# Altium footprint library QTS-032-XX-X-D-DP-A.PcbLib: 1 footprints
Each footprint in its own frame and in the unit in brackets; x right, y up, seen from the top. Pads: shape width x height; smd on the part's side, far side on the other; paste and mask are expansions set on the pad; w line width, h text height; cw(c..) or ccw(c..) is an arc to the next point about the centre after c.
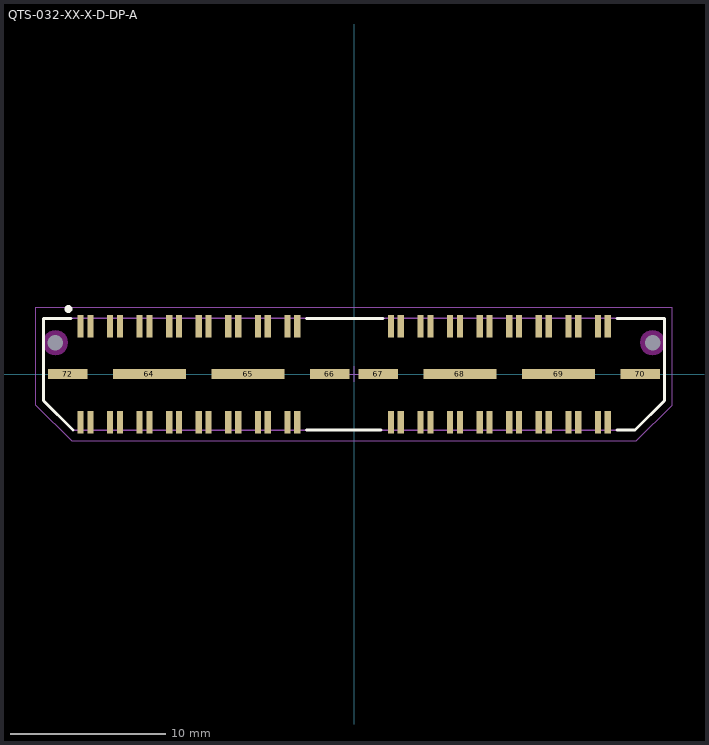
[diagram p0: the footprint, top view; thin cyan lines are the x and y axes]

## QTS-032-XX-X-D-DP-A [mm] "0.635mm pitch, 64 pin, high speed terminal; differential pair array"
height 4.27
pads (74):
  rect 0.4x1.45 smd mask+0: 1(-17.621,3.086) 2(-17.621,-3.086) 3(-16.986,3.086) 4(-16.986,-3.086) 5(-15.716,3.086) 6(-15.716,-3.086) 7(-15.081,3.086) 8(-15.081,-3.086) 9(-13.811,3.086) 10(-13.811,-3.086) 11(-13.176,3.086) 12(-13.176,-3.086) 13(-11.906,3.086) 14(-11.906,-3.086) 15(-11.271,3.086) 16(-11.271,-3.086) 17(-10.001,3.086) 18(-10.001,-3.086) 19(-9.366,3.086) 20(-9.366,-3.086) 21(-8.096,3.086) 22(-8.096,-3.086) 23(-7.461,3.086) 24(-7.461,-3.086) 25(-6.191,3.086) 26(-6.191,-3.086) 27(-5.556,3.086) 28(-5.556,-3.086) 29(-4.286,3.086) 30(-4.286,-3.086) 31(-3.651,3.086) 32(-3.651,-3.086) 33(2.381,3.086) 34(2.381,-3.086) 35(3.016,3.086) 36(3.016,-3.086) 37(4.286,3.086) 38(4.286,-3.086) 39(4.921,3.086) 40(4.921,-3.086) 41(6.191,3.086) 42(6.191,-3.086) 43(6.826,3.086) 44(6.826,-3.086) 45(8.096,3.086) 46(8.096,-3.086) 47(8.731,3.086) 48(8.731,-3.086) 49(10.001,3.086) 50(10.001,-3.086) 51(10.636,3.086) 52(10.636,-3.086) 53(11.906,3.086) 54(11.906,-3.086) 55(12.541,3.086) 56(12.541,-3.086) 57(13.811,3.086) 58(13.811,-3.086) 59(14.446,3.086) 60(14.446,-3.086) 61(15.716,3.086) 62(15.716,-3.086) 63(16.351,3.086) 71(16.351,-3.086)
  rect 4.7x0.65 smd mask+0: 64(-13.176,0) 65(-6.826,0) 68(6.826,0) 69(13.176,0)
  rect 2.55x0.65 smd mask+0: 66(-1.556,0) 67(1.556,0) 70(18.447,0) 72(-18.447,0)
  round 0.5 hole 1 unplated mask+0: 73(-19.241,2.032) 74(19.241,2.032)
Top Overlay:
  circle w0.25: c-18.4,4.2 r0.125
  lines w0.2: -18.25,3.6 -20,3.6 -20,-1.7 -18.1,-3.6 ; -3.05,-3.6 1.75,-3.6 ; -3.05,3.6 1.85,3.6 ; 16.95,-3.6 18.1,-3.6 20,-1.7 20,3.6 16.95,3.6
Keep-Out Layer:
  pour cut-out: -18.434,2.032 -18.462,2.241 -18.542,2.435 -18.67,2.603 -18.838,2.731 -19.032,2.811 -19.241,2.839 -19.45,2.811 -19.644,2.731 -19.812,2.603 -19.94,2.435 -20.02,2.241 -20.048,2.032 -20.02,1.823 -19.94,1.629 -19.812,1.461 -19.644,1.333 -19.45,1.253 -19.241,1.225 -19.032,1.253 -18.838,1.333 -18.67,1.461 -18.542,1.629 -18.462,1.823
  pour cut-out: 20.048,2.032 20.02,2.241 19.94,2.435 19.812,2.603 19.644,2.731 19.45,2.811 19.241,2.839 19.032,2.811 18.838,2.731 18.67,2.603 18.542,2.435 18.462,2.241 18.434,2.032 18.462,1.823 18.542,1.629 18.67,1.461 18.838,1.333 19.032,1.253 19.241,1.225 19.45,1.253 19.644,1.333 19.812,1.461 19.94,1.629 20.02,1.823
Mechanical 12:
  lines w0.001: -20,-1.7 -20,3.6 20,3.6 20,-1.7 18.1,-3.6 -18.1,-3.6 -20,-1.7
Mechanical 13:
  lines w0.1: -20,-1.7 -20,3.6 20,3.6 20,-1.7 18.1,-3.6 -18.1,-3.6 -20,-1.7
  text ".Designator" at 0,0 h1.52
Mechanical 15:
  lines w0.05: -0.5,0 0.5,0 ; 0,-0.5 0,0.5 ; -20.5,-2 -20.5,4.3 20.5,4.3 20.5,-2 18.2,-4.3 -18.2,-4.3 -20.5,-2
